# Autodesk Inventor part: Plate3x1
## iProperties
Created: 2006-02
Part Number: Plate3x1
Material: Stainless Steel
Document SubType Name: Modeling
Designer: 40664
Mass: 189072 g
Surface Area: 47430 cm^2
Volume: 23400 cm^3
Density: 8.08 g/cm^3
CSToolsMass: 189.0
CSToolsVolume: 23400000.0
CSToolsArea: 47430.0
Author: 40664
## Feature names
1. Extrusion2
